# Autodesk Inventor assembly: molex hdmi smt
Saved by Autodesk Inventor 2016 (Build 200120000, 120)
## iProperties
Created: 2018-05
Part Number: molex hdmi smt
Document SubType Name: Assembly
Designer: Administrator
Title: molex hdmi smt v8
Author: Administrator
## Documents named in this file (3)
- c:\worker\convert-fusion-mar-2018\tmp\job-1\16\output\files\8c58ff39-88bb-4352-afd9-60265520bae5\molex hdmi smt v8.iam
- c:\worker\convert-fusion-mar-2018\tmp\job-1\16\output\files\8c58ff39-88bb-4352-afd9-60265520bae5\Component2_2.ipt
- c:\worker\convert-fusion-mar-2018\tmp\job-1\16\output\files\8c58ff39-88bb-4352-afd9-60265520bae5\molex hdmi smt v8.ipt
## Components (2 placed, 2 different names)
1. Component2:1
2. molex hdmi smt v8
